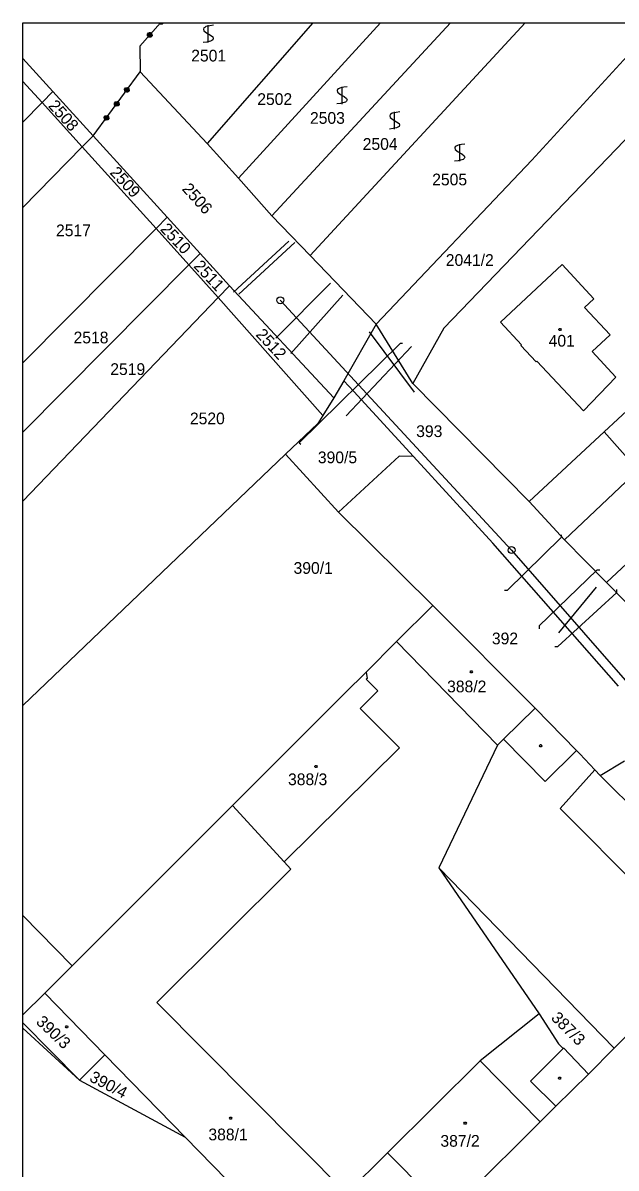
# Model space of a CAD drawing. Extents: x -639621 to -639329, y -1192893 to -1192488.
# Drawn here: x -639621.3 to -639535.3, y -1192653.7 to -1192487.8 of the extents above; entities that cross this region are included whole.
import ezdxf

# ---------------------------------------------------------------- set-up
doc = ezdxf.new("R2010")
doc.units = 0
for name, color, linetype in [('Vrstva 1', 7, 'Continuous'), ('Vrstva 19', 7, 'Continuous'), ('Vrstva 2', 7, 'Continuous'), ('Vrstva 21', 7, 'Continuous'), ('Vrstva 24', 7, 'Continuous'), ('Vrstva 25', 7, 'Continuous'), ('Vrstva 3', 7, 'Continuous'), ('Vrstva 4', 7, 'Continuous'), ('Vrstva 5', 7, 'Continuous'), ('Vrstva 61', 7, 'Continuous')]:
    doc.layers.add(name, color=color, linetype=linetype)

msp = doc.modelspace()

# ---------------------------------------------------------------- linework, layer by layer
at = {"layer": 'Vrstva 1'}
for p, q in [((-639601.33, -1192487.83), (-639604.33, -1192491.21)), ((-639579.25, -1192487.83), (-639594.57, -1192505.29)), ((-639590.01, -1192510.33), (-639569.44, -1192487.83)), ((-639585.18, -1192515.76), (-639559.3, -1192487.83)), ((-639548.46, -1192487.83), (-639579.63, -1192521.52)), ((-639547.5, -1192507.7), (-639529.28, -1192487.83)), ((-639604.33, -1192491.21), (-639604.27, -1192494.9)), ((-639616.93, -1192497.77), (-639621.26, -1192493.01)), ((-639611.08, -1192504.2), (-639604.27, -1192494.9)), ((-639604.27, -1192494.9), (-639594.57, -1192505.29)), ((-639621.26, -1192496.32), (-639618.49, -1192499.37)), ((-639618.49, -1192499.37), (-639616.93, -1192497.77)), ((-639611.08, -1192504.2), (-639616.93, -1192497.77)), ((-639618.49, -1192499.37), (-639621.26, -1192502.2)), ((-639618.49, -1192499.37), (-639612.65, -1192505.79)), ((-639529.73, -1192500.3), (-639560.27, -1192532.04)), ((-639612.65, -1192505.79), (-639611.08, -1192504.2)), ((-639600.36, -1192515.98), (-639611.08, -1192504.2)), ((-639594.57, -1192505.29), (-639590.01, -1192510.33)), ((-639621.26, -1192514.55), (-639612.65, -1192505.79)), ((-639612.65, -1192505.79), (-639601.96, -1192517.59)), ((-639570.05, -1192531.45), (-639547.5, -1192507.7)), ((-639590.01, -1192510.33), (-639585.18, -1192515.76)), ((-639601.96, -1192517.59), (-639600.36, -1192515.98)), ((-639595.57, -1192521.25), (-639600.36, -1192515.98)), ((-639579.63, -1192521.52), (-639585.18, -1192515.76)), ((-639601.96, -1192517.59), (-639621.26, -1192537.09)), ((-639601.96, -1192517.59), (-639597.2, -1192522.89)), ((-639597.2, -1192522.89), (-639595.57, -1192521.25)), ((-639591.33, -1192525.9), (-639595.57, -1192521.25)), ((-639579.63, -1192521.52), (-639570.05, -1192531.45)), ((-639621.26, -1192547.09), (-639597.2, -1192522.89)), ((-639597.2, -1192522.89), (-639592.96, -1192527.6)), ((-639543.13, -1192522.82), (-639552.05, -1192531.18)), ((-639538.51, -1192527.78), (-639543.13, -1192522.82)), ((-639591.33, -1192525.9), (-639592.96, -1192527.6)), ((-639576.18, -1192542.14), (-639591.33, -1192525.9)), ((-639592.96, -1192527.6), (-639621.26, -1192557.11)), ((-639577.8, -1192544.69), (-639592.96, -1192527.6)), ((-639539.86, -1192529.04), (-639538.51, -1192527.78)), ((-639536.15, -1192533.02), (-639539.86, -1192529.04)), ((-639570.05, -1192531.45), (-639574.76, -1192539.66)), ((-639564.74, -1192540.08), (-639570.05, -1192531.45)), ((-639560.27, -1192532.04), (-639564.74, -1192540.08)), ((-639552.05, -1192531.18), (-639548.99, -1192534.45)), ((-639538.75, -1192535.44), (-639536.15, -1192533.02)), ((-639548.99, -1192534.45), (-639549.12, -1192534.56)), ((-639549.12, -1192534.56), (-639546.9, -1192536.94)), ((-639535.35, -1192539.16), (-639538.75, -1192535.44)), ((-639546.77, -1192536.83), (-639546.9, -1192536.94)), ((-639546.77, -1192536.83), (-639540.04, -1192544.03)), ((-639574.76, -1192539.66), (-639576.18, -1192542.14)), ((-639574.76, -1192539.66), (-639573.32, -1192541.22)), ((-639547.9, -1192557.16), (-639564.74, -1192540.08)), ((-639540.04, -1192544.03), (-639535.35, -1192539.16)), ((-639564.65, -1192550.62), (-639573.32, -1192541.22)), ((-639576.18, -1192542.14), (-639577.8, -1192544.69)), ((-639537.05, -1192547.08), (-639533.05, -1192543.41)), ((-639577.8, -1192544.69), (-639578.54, -1192545.86)), ((-639578.54, -1192545.86), (-639583.2, -1192550.31)), ((-639547.9, -1192557.16), (-639537.05, -1192547.08)), ((-639583.2, -1192550.31), (-639621.26, -1192586.7)), ((-639583.2, -1192550.31), (-639575.54, -1192558.69)), ((-639575.54, -1192558.69), (-639566.76, -1192550.59)), ((-639564.65, -1192550.62), (-639566.76, -1192550.59)), ((-639553.16, -1192563.18), (-639564.65, -1192550.62)), ((-639542.8, -1192562.7), (-639532.09, -1192552.6)), ((-639561.85, -1192572.23), (-639575.54, -1192558.69)), ((-639542.8, -1192562.7), (-639547.9, -1192557.16)), ((-639526.21, -1192559.01), (-639536.67, -1192568.89)), ((-639534.95, -1192583.89), (-639553.16, -1192563.18)), ((-639536.67, -1192568.89), (-639542.8, -1192562.7)), ((-639525.7, -1192580.15), (-639536.67, -1192568.89)), ((-639567.14, -1192577.45), (-639561.85, -1192572.23)), ((-639547.02, -1192587.1), (-639561.85, -1192572.23)), ((-639571.54, -1192581.86), (-639567.14, -1192577.45)), ((-639552.51, -1192592.45), (-639567.14, -1192577.45)), ((-639574.6, -1192584.92), (-639571.54, -1192581.86)), ((-639571.54, -1192581.86), (-639571.38, -1192582.77)), ((-639571.38, -1192582.77), (-639571.5, -1192582.89)), ((-639571.5, -1192582.89), (-639569.81, -1192584.58)), ((-639590.87, -1192601.18), (-639574.6, -1192584.92)), ((-639569.81, -1192584.58), (-639572.38, -1192587.14)), ((-639566.71, -1192592.83), (-639572.38, -1192587.14)), ((-639547.02, -1192587.1), (-639551.6, -1192591.57)), ((-639541.04, -1192593.2), (-639547.02, -1192587.1)), ((-639551.6, -1192591.57), (-639552.51, -1192592.45)), ((-639566.71, -1192592.83), (-639583.4, -1192609.34)), ((-639552.51, -1192592.45), (-639560.98, -1192610.22)), ((-639540.55, -1192593.7), (-639541.04, -1192593.2)), ((-639538.37, -1192596.04), (-639540.55, -1192593.7)), ((-639537.59, -1192596.82), (-639534.06, -1192594.73)), ((-639537.59, -1192596.82), (-639538.37, -1192596.04)), ((-639614.11, -1192624.41), (-639590.87, -1192601.18)), ((-639583.4, -1192609.34), (-639590.87, -1192601.18)), ((-639560.98, -1192610.22), (-639546.46, -1192631.38)), ((-639560.98, -1192610.22), (-639535.58, -1192636.31)), ((-639621.26, -1192617.1), (-639614.11, -1192624.41)), ((-639535.58, -1192636.31), (-639522.28, -1192622.87)), ((-639618.09, -1192628.37), (-639614.11, -1192624.41)), ((-639618.09, -1192628.37), (-639621.26, -1192631.52)), ((-639609.37, -1192637.29), (-639618.09, -1192628.37)), ((-639546.46, -1192631.38), (-639555.01, -1192638.16)), ((-639546.46, -1192631.38), (-639543.67, -1192635.71)), ((-639621.26, -1192632.68), (-639613.04, -1192640.98)), ((-639621.26, -1192633.45), (-639613.04, -1192640.98)), ((-639543.67, -1192635.71), (-639542.99, -1192636.37)), ((-639542.99, -1192636.37), (-639542.91, -1192636.29)), ((-639542.91, -1192636.29), (-639539.32, -1192640.09)), ((-639539.32, -1192640.09), (-639535.58, -1192636.31)), ((-639613.04, -1192640.98), (-639609.37, -1192637.29)), ((-639597.73, -1192649.2), (-639609.37, -1192637.29)), ((-639555.01, -1192638.16), (-639568.41, -1192651.47)), ((-639613.04, -1192640.98), (-639597.73, -1192649.2)), ((-639544.04, -1192644.73), (-639539.32, -1192640.09)), ((-639546.32, -1192646.99), (-639544.04, -1192644.73)), ((-639559.67, -1192660.27), (-639546.32, -1192646.99)), ((-639587.88, -1192659.28), (-639597.73, -1192649.2)), ((-639568.41, -1192651.47), (-639559.67, -1192660.27))]:
    msp.add_line(p, q, dxfattribs=at)
for points in [[(-639601.06, -1192488.01), (-639601.33, -1192488.03), (-639601.53, -1192487.85), (-639601.53, -1192487.83)], [(-639601.49, -1192487.83), (-639601.49, -1192487.83), (-639601.49, -1192487.83)], [(-639601.28, -1192487.83), (-639601.37, -1192487.94), (-639601.43, -1192487.89), (-639601.38, -1192487.83)], [(-639601.06, -1192487.83), (-639601.2, -1192487.99), (-639601.31, -1192487.99), (-639601.17, -1192487.83)], [(-639600.9, -1192487.83), (-639601.06, -1192488.01), (-639601.08, -1192487.98), (-639600.95, -1192487.83)], [(-639602.73, -1192489.89), (-639603, -1192489.91), (-639603.2, -1192489.73), (-639603.21, -1192489.46), (-639603.04, -1192489.26), (-639602.77, -1192489.24), (-639602.57, -1192489.42), (-639602.55, -1192489.69), (-639602.73, -1192489.89), (-639602.73, -1192489.83), (-639602.57, -1192489.66), (-639602.59, -1192489.56), (-639602.84, -1192489.84), (-639602.96, -1192489.85), (-639602.61, -1192489.46), (-639602.67, -1192489.41), (-639603.02, -1192489.79), (-639603.08, -1192489.74), (-639602.73, -1192489.35), (-639602.79, -1192489.29), (-639603.13, -1192489.68), (-639603.16, -1192489.6), (-639602.89, -1192489.29), (-639602.98, -1192489.28), (-639603.14, -1192489.46)], [(-639606.37, -1192497.22), (-639606.1, -1192497.18), (-639605.89, -1192497.34), (-639605.84, -1192497.61), (-639606, -1192497.82), (-639606.27, -1192497.86), (-639606.49, -1192497.71), (-639606.53, -1192497.44), (-639606.37, -1192497.22), (-639606.36, -1192497.28), (-639606.5, -1192497.47), (-639606.47, -1192497.57), (-639606.25, -1192497.26), (-639606.14, -1192497.24), (-639606.44, -1192497.66), (-639606.38, -1192497.71), (-639606.07, -1192497.29), (-639606.01, -1192497.34), (-639606.31, -1192497.76), (-639606.26, -1192497.81), (-639605.95, -1192497.39), (-639605.91, -1192497.47), (-639606.15, -1192497.8), (-639606.06, -1192497.81), (-639605.91, -1192497.62)], [(-639607.85, -1192499.25), (-639607.58, -1192499.21), (-639607.37, -1192499.37), (-639607.33, -1192499.63), (-639607.48, -1192499.85), (-639607.75, -1192499.89), (-639607.97, -1192499.73), (-639608.01, -1192499.47), (-639607.85, -1192499.25), (-639607.82, -1192499.28), (-639607.97, -1192499.47), (-639607.95, -1192499.58), (-639607.71, -1192499.26), (-639607.6, -1192499.25), (-639607.93, -1192499.7), (-639607.87, -1192499.74), (-639607.54, -1192499.29), (-639607.47, -1192499.34), (-639607.8, -1192499.79), (-639607.74, -1192499.84), (-639607.41, -1192499.39), (-639607.39, -1192499.5), (-639607.63, -1192499.82), (-639607.51, -1192499.8), (-639607.37, -1192499.61)], [(-639609.33, -1192501.27), (-639609.07, -1192501.23), (-639608.85, -1192501.39), (-639608.81, -1192501.66), (-639608.97, -1192501.88), (-639609.23, -1192501.92), (-639609.45, -1192501.76), (-639609.49, -1192501.49), (-639609.33, -1192501.27), (-639609.3, -1192501.29), (-639609.44, -1192501.48), (-639609.42, -1192501.59), (-639609.18, -1192501.27), (-639609.08, -1192501.27), (-639609.4, -1192501.71), (-639609.34, -1192501.75), (-639609.02, -1192501.33), (-639608.95, -1192501.36), (-639609.27, -1192501.79), (-639609.2, -1192501.84), (-639608.89, -1192501.41), (-639608.85, -1192501.5), (-639609.11, -1192501.85), (-639609, -1192501.84), (-639608.84, -1192501.61)]]:
    msp.add_lwpolyline(points, dxfattribs=at)
at = {"layer": 'Vrstva 19'}
msp.add_lwpolyline([(-639583.96, -1192528.01), (-639550.45, -1192564.18), (-639529.58, -1192588.03), (-639514.49, -1192612.05), (-639507.74, -1192644.33), (-639498.83, -1192694.25), (-639511.44, -1192713.33), (-639516.61, -1192716.51), (-639553.94, -1192703.74), (-639570.48, -1192701.62), (-639578.69, -1192703.18)], dxfattribs=at)
for centre in [(-639583.96, -1192528.01), (-639550.45, -1192564.18)]:
    msp.add_circle(centre, 0.5, dxfattribs=at)
at = {"layer": 'Vrstva 21'}
for p, q in [((-639576.7, -1192525.55), (-639584.61, -1192533.51)), ((-639574.91, -1192527.29), (-639582.43, -1192535.72)), ((-639571.1, -1192532.56), (-639564.58, -1192541.34))]:
    msp.add_line(p, q, dxfattribs=at)
at = {"layer": 'Vrstva 24'}
for points in [[(-639566.27, -1192534.26), (-639566.57, -1192534.26), (-639581.21, -1192548.66), (-639581, -1192548.87)], [(-639543.27, -1192561.96), (-639543.27, -1192562.38), (-639551.07, -1192570.03), (-639551.49, -1192570.03)], [(-639537.66, -1192567.11), (-639538.08, -1192567.1), (-639546.44, -1192575.17), (-639546.45, -1192575.6)], [(-639544.17, -1192578.16), (-639543.74, -1192578.17), (-639535.21, -1192570.34), (-639535.19, -1192569.92)]]:
    msp.add_lwpolyline(points, dxfattribs=at)
at = {"layer": 'Vrstva 25'}
for p, q in [((-639582.73, -1192519.46), (-639590.76, -1192526.83)), ((-639581.86, -1192519.66), (-639589.96, -1192527.1)), ((-639564.96, -1192534.71), (-639574.41, -1192544.74)), ((-639538.2, -1192569.57), (-639543.67, -1192576.17))]:
    msp.add_line(p, q, dxfattribs=at)
at = {"layer": 'Vrstva 3'}
for points in [[(-639593.64, -1192488.18), (-639594.15, -1192488.24), (-639594.5, -1192488.29), (-639594.74, -1192488.37), (-639594.92, -1192488.48), (-639595.04, -1192488.57), (-639595.09, -1192488.74), (-639595.04, -1192488.97), (-639594.65, -1192489.29), (-639594.09, -1192489.6), (-639593.74, -1192489.87), (-639593.67, -1192490.07), (-639593.74, -1192490.27), (-639593.9, -1192490.4), (-639594.09, -1192490.47), (-639594.62, -1192490.6), (-639595.14, -1192490.67)], [(-639594.39, -1192490.68), (-639594.39, -1192489.41), (-639594.39, -1192488.18)], [(-639574.25, -1192497.08), (-639574.76, -1192497.14), (-639575.11, -1192497.19), (-639575.35, -1192497.27), (-639575.53, -1192497.38), (-639575.65, -1192497.47), (-639575.7, -1192497.64), (-639575.65, -1192497.87), (-639575.26, -1192498.19), (-639574.7, -1192498.5), (-639574.35, -1192498.77), (-639574.28, -1192498.97), (-639574.35, -1192499.17), (-639574.51, -1192499.3), (-639574.7, -1192499.37), (-639575.23, -1192499.5), (-639575.75, -1192499.57)], [(-639575, -1192499.58), (-639575, -1192498.31), (-639575, -1192497.08)], [(-639566.65, -1192500.73), (-639567.16, -1192500.79), (-639567.51, -1192500.84), (-639567.75, -1192500.92), (-639567.93, -1192501.03), (-639568.05, -1192501.12), (-639568.1, -1192501.29), (-639568.05, -1192501.52), (-639567.66, -1192501.84), (-639567.1, -1192502.15), (-639566.75, -1192502.42), (-639566.68, -1192502.62), (-639566.75, -1192502.82), (-639566.91, -1192502.95), (-639567.1, -1192503.02), (-639567.63, -1192503.15), (-639568.15, -1192503.22)], [(-639567.4, -1192503.23), (-639567.4, -1192501.96), (-639567.4, -1192500.73)], [(-639557.2, -1192505.38), (-639557.71, -1192505.44), (-639558.06, -1192505.49), (-639558.3, -1192505.57), (-639558.48, -1192505.68), (-639558.6, -1192505.77), (-639558.65, -1192505.94), (-639558.6, -1192506.17), (-639558.21, -1192506.49), (-639557.65, -1192506.8), (-639557.3, -1192507.07), (-639557.23, -1192507.27), (-639557.3, -1192507.47), (-639557.46, -1192507.6), (-639557.65, -1192507.67), (-639558.18, -1192507.8), (-639558.7, -1192507.87)], [(-639557.95, -1192507.88), (-639557.95, -1192506.61), (-639557.95, -1192505.38)]]:
    msp.add_lwpolyline(points, dxfattribs=at)
at = {"layer": 'Vrstva 4'}
for p, q in [((-639537.05, -1192547.08), (-639532.09, -1192552.6)), ((-639551.6, -1192591.57), (-639545.58, -1192597.71)), ((-639541.04, -1192593.2), (-639545.58, -1192597.71)), ((-639543.41, -1192601.63), (-639538.37, -1192596.04)), ((-639516.92, -1192617.59), (-639537.59, -1192596.82)), ((-639522.28, -1192622.87), (-639543.41, -1192601.63)), ((-639582.44, -1192610.4), (-639583.4, -1192609.34)), ((-639601.86, -1192629.73), (-639582.44, -1192610.4)), ((-639574.37, -1192657.4), (-639601.86, -1192629.73)), ((-639542.99, -1192636.37), (-639547.7, -1192641.09)), ((-639546.32, -1192646.99), (-639555.01, -1192638.16)), ((-639547.7, -1192641.09), (-639544.04, -1192644.73)), ((-639568.41, -1192651.47), (-639574.37, -1192657.4))]:
    msp.add_line(p, q, dxfattribs=at)
at = {"layer": 'Vrstva 5'}
for points in [[(-639543.35, -1192532.08), (-639543.26, -1192532.23), (-639543.35, -1192532.38), (-639543.53, -1192532.38), (-639543.62, -1192532.23), (-639543.53, -1192532.08)], [(-639556.19, -1192581.66), (-639556.1, -1192581.81), (-639556.19, -1192581.96), (-639556.37, -1192581.96), (-639556.46, -1192581.81), (-639556.37, -1192581.66)], [(-639546.14, -1192592.37), (-639546.05, -1192592.52), (-639546.14, -1192592.67), (-639546.32, -1192592.67), (-639546.41, -1192592.52), (-639546.32, -1192592.37)], [(-639578.71, -1192595.38), (-639578.62, -1192595.53), (-639578.71, -1192595.68), (-639578.89, -1192595.68), (-639578.98, -1192595.53), (-639578.89, -1192595.38)], [(-639614.82, -1192633.09), (-639614.73, -1192633.24), (-639614.82, -1192633.39), (-639615, -1192633.39), (-639615.09, -1192633.24), (-639615, -1192633.09)], [(-639543.4, -1192640.51), (-639543.31, -1192640.66), (-639543.4, -1192640.81), (-639543.58, -1192640.81), (-639543.67, -1192640.66), (-639543.58, -1192640.51)], [(-639591.06, -1192646.31), (-639590.97, -1192646.46), (-639591.06, -1192646.61), (-639591.24, -1192646.61), (-639591.33, -1192646.46), (-639591.24, -1192646.31)], [(-639557.09, -1192647.03), (-639557, -1192647.18), (-639557.09, -1192647.33), (-639557.27, -1192647.33), (-639557.36, -1192647.18), (-639557.27, -1192647.03)]]:
    msp.add_lwpolyline(points, close=True, dxfattribs=at)
at = {"layer": 'Vrstva 61'}
for points in [[(-639621.26, -1192893.33), (-639621.26, -1192487.83)], [(-639621.26, -1192487.83), (-639329.26, -1192487.83)]]:
    msp.add_lwpolyline(points, dxfattribs=at)

# ---------------------------------------------------------------- texts
at = {"layer": 'Vrstva 2'}
for s, p in [('2501', (-639596.87, -1192493.42)), ('2502', (-639587.3, -1192499.72)), ('2503', (-639579.66, -1192502.45)), ('2504', (-639572.02, -1192506.22)), ('2505', (-639561.95, -1192511.36)), ('2517', (-639616.46, -1192518.73)), ('2041/2', (-639559.98, -1192523.03)), ('2518', (-639613.92, -1192534.25)), ('401', (-639545.07, -1192534.72)), ('2519', (-639608.6, -1192538.83)), ('2520', (-639597.06, -1192545.97)), ('393', (-639564.27, -1192547.82)), ('390/5', (-639578.52, -1192551.61)), ('390/1', (-639582.04, -1192567.63)), ('392', (-639553.3, -1192577.84)), ('388/2', (-639559.79, -1192584.79)), ('388/3', (-639582.84, -1192598.24)), ('388/1', (-639594.38, -1192649.68)), ('387/2', (-639560.76, -1192650.61))]:
    msp.add_text(s, height=1.7, dxfattribs=at).set_placement(p)
for s, rotation, p in [('2508', 311.8609, (-639617.68, -1192499.91)), ('2509', 312.7204, (-639608.76, -1192509.59)), ('2506', 312.0901, (-639598.3, -1192511.95)), ('2510', 313.1787, (-639601.46, -1192517.79)), ('2511', 312.835, (-639596.61, -1192523.14)), ('2512', 312.7777, (-639587.61, -1192533.05)), ('390/3', 316.5019, (-639619.47, -1192632.66)), ('387/3', 315.0695, (-639544.83, -1192632.07)), ('390/4', 332.3155, (-639611.75, -1192641.04))]:
    msp.add_text(s, height=1.7, rotation=rotation, dxfattribs=at).set_placement(p)

doc.saveas('drawing.dxf')
